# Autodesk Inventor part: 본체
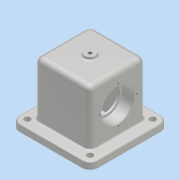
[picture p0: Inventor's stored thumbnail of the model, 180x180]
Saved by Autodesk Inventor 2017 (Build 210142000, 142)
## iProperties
Part Number: 본체
Material: 알루미늄 6061
Document SubType Name: Modeling
Designer: MRC
Density: 2.7 g/cm^3
Appearance: 알루미늄 - 평지
Mass: 1059.83 g
Surface Area: 721.846 cm^2
Volume: 392.53 cm^3
Author: MRC
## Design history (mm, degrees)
sketch "스케치1"
  geometry: L1 (-58, 58)-(58, 58); L2 (58, 58)-(58, -58); L3 (58, -58)-(-58, -58); L4 (-58, -58)-(-58, 58); L5 (-58, 58)-(58, -58); L6 (58, 58)-(-58, -58); 1 further point
  constraints: 12 end point, 2 midpoint, 2 parallel, 1 horizontal, 1 perpendicular
  dimensions: "d0" = 116 distance between parallel lines of L3 L1; "d1" = 116 distance between parallel lines of L2 L4
extrude "돌출1" new body sketch "스케치1" distance "d2" = 10; taper "d3" = 0 deg
sketch "스케치2"
  geometry: L1 (-41, 41)-(41, 41); L2 (41, 41)-(41, -41); L3 (41, -41)-(-41, -41); L4 (-41, -41)-(-41, 41); L5 (-41, 41)-(41, -41); L6 (41, 41)-(-41, -41); 1 further point
  constraints: 12 end point, 2 midpoint, 2 parallel, 1 horizontal, 1 perpendicular
  dimensions: "d4" = 82 distance of L2.end L3.end; "d5" = 82 distance of L1.end L2.end
extrude "돌출2" join sketch "스케치2" distance "d6" = 80; taper "d7" = 0 deg
sketch "스케치3"
  geometry: L1 (-21, 30)-(21, 30); L2 (21, 30)-(21, -30); L3 (21, -30)-(-21, -30); L4 (-21, -30)-(-21, 30); L5 (-21, 30)-(21, -30); L6 (21, 30)-(-21, -30); 3 further points
  constraints: 12 end point, 3 midpoint, 2 parallel, 1 coincident, 1 horizontal, 1 perpendicular
  dimensions: "d8" = 60 distance between parallel lines of L3 L1; "d9" = 42 distance between parallel lines of L4 L2
extrude "돌출3" cut sketch "스케치3" distance "d10" = 80; taper "d11" = 0 deg
sketch "스케치4"
  geometry: L1 (10, 41)-(-38, 41); C1 r 23.5 at (-38, 41)
  constraints: 2 end point, 1 centre point, 1 coincident, 1 horizontal
  dimensions: "d12" = 47 diameter of C1; "d13" = 48 distance of L1.start L1.end
extrude "돌출4" cut sketch "스케치4" distance "d14" = 17; taper "d15" = 0 deg
sketch "스케치5"
  geometry: C1 r 20 at (0, 0); C2 r 23.5 at (0, 0) reference; 1 further point
  constraints: 1 centre point, 1 concentric
  dimensions: "d16" = 40 diameter of C1
extrude "돌출5" cut sketch "스케치5" distance "d17" = 10; taper "d18" = 0 deg
sketch "스케치6"
  geometry: L1 (-65, 41)-(-11, 41); C1 r 23.5 at (-38, 41) reference; A1 r 27 centre (-38, 41) between (-65, 41) and (-11, 41); 2 further points
  constraints: 3 point on circle, 2 end point, 1 centre point, 1 concentric, 1 horizontal, 1 midpoint, 1 point on line
  dimensions: "d19" = 54 diameter of A1
hole "구멍1" sketch "스케치6" at (-65, 41) diameter "d20" = 3.242; stored, may be unused: countersink angle "d24" = 90 deg, drill point angle "d26" = 118 deg; dims "d21" = 8, "d22" = 4, "d23" = 2, "d25" = 10
sketch "스케치7"
  geometry: C1 r 7.5 at (0, 0); 1 further point
  constraints: 1 centre point, 1 coincident
  dimensions: "d30" = 15 diameter of C1
extrude "돌출6" join sketch "스케치7" distance "d31" = 4; taper "d32" = 0 deg
sketch "스케치8"
  geometry: 2 further points
  constraints: 1 coincident
hole "구멍2" sketch "스케치8" at (0, 0) diameter "d33" = 4.917; stored, may be unused: countersink angle "d37" = 90 deg, drill point angle "d39" = 0 deg; dims "d34" = 14, "d35" = 4, "d36" = 2, "d38" = 14
fillet "모깎기1" dims "d40" = 0.6
chamfer "모따기1" distance "d41" = 1; stored, may be unused: second distance "d42" = 2, angle "d43" = 45 deg
fillet "모깎기2" dims "d44" = 8
sketch "스케치9"
  geometry: L1 (-58, 58)-(-58, -58) reference; L2 (58, 58)-(-58, 58) reference; C1 r 4.5 at (-46, 46); 1 further point
  constraints: 1 centre point
  dimensions: "d45" = 9 diameter of C1; "d46" = 12 distance from line of L1 C1.centre; "d47" = 12 distance from line of C1.centre L2
extrude "돌출7" cut sketch "스케치9" distance "d48" = 10; taper "d49" = 0 deg
fillet "모깎기3" dims "d56" = 12
fillet "모깎기4" dims "d57" = 3
fillet "모깎기5" dims "d58" = 3
sketch "스케치10"
  geometry: L1 (-13, 82)-(79, 82) reference; L2 (33, 82)-(33, 34); 1 further point
  constraints: 2 end point, 1 coincident, 1 vertical, 1 other
  dimensions: "d59" = 48 distance of L2.start L2.end
feature "엠보싱1" sketch "스케치10" dims "d0" = 116, "d1" = 116, "d8" = 60, "d9" = 42, "d60" = 0.5, "d61" = 0
fillet "모깎기6" dims "d62" = 3
node "솔리드1"
pattern_circular "원형 패턴1" dims angle "d28" = 360 deg
mirror "미러1"
pattern_linear "직사각형 패턴1" dims "d52" = 92, "d55" = 92
